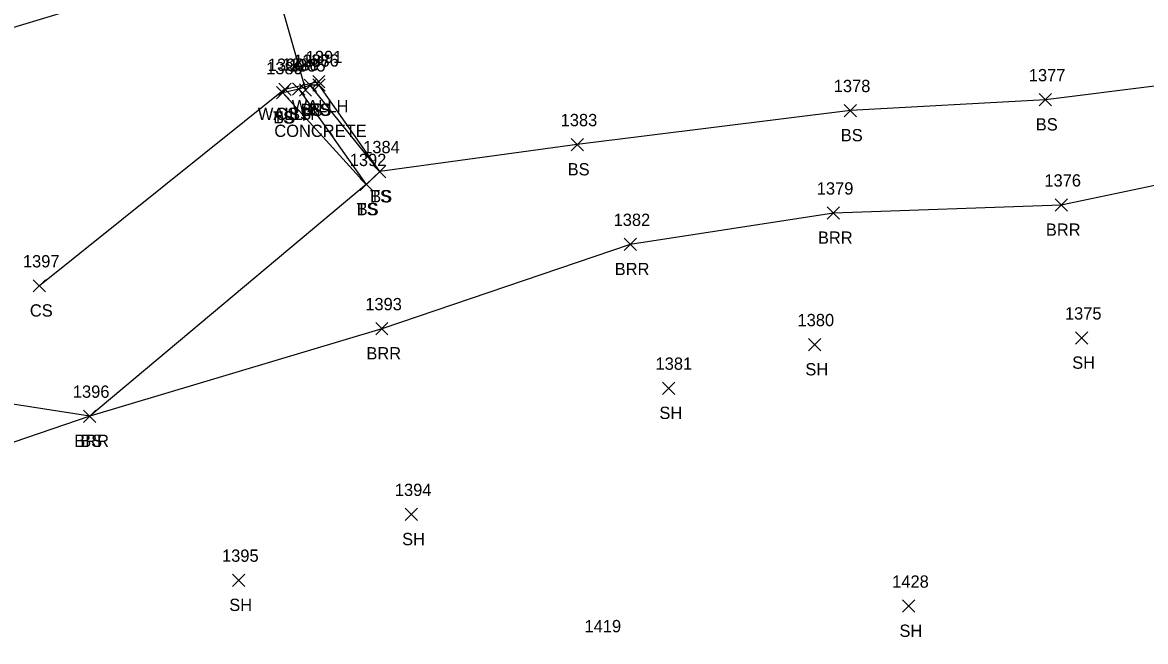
# Model space of a CAD drawing. Extents: x 1599569 to 1610055, y 642560 to 647860.
# Drawn here: x 1602081.3 to 1602263.8, y 647296.9 to 647397.5 of the extents above; entities that cross this region are included whole.
import ezdxf

# ---------------------------------------------------------------- set-up
doc = ezdxf.new("R2010")
doc.units = 0
for name, color, linetype in [('D_A', 7, 'Continuous'), ('D_C', 7, 'Continuous'), ('D_I', 7, 'Continuous'), ('D_TIC', 7, 'Continuous'), ('DCP', 7, 'Continuous'), ('DHW', 7, 'Continuous'), ('L_A', 7, 'Continuous'), ('L_I', 7, 'Continuous'), ('L_TIC', 7, 'Continuous'), ('LABL', 7, 'Continuous'), ('LELB', 7, 'Continuous')]:
    doc.layers.add(name, color=color, linetype=linetype)

msp = doc.modelspace()

# ---------------------------------------------------------------- linework, layer by layer
at = {"layer": 'D_TIC'}
for points in [[(1602128.44, 647386.93), (1602130.44, 647388.93)], [(1602130.44, 647386.93), (1602128.44, 647388.93)], [(1602122.92, 647385.68), (1602124.92, 647387.68)], [(1602124.92, 647385.68), (1602122.92, 647387.68)], [(1602126.27, 647385.57), (1602128.27, 647387.57)], [(1602128.27, 647385.57), (1602126.27, 647387.57)]]:
    msp.add_lwpolyline(points, dxfattribs=at)
at = {"layer": 'DCP'}
msp.add_lwpolyline([(1602103.84, 647468.61), (1602127.27, 647386.57)], dxfattribs=at)
at = {"layer": 'DHW'}
msp.add_lwpolyline([(1602123.92, 647386.68), (1602129.44, 647387.93)], dxfattribs=at)
at = {"layer": 'L_TIC'}
for points in [[(1602122.58, 647385.12), (1602124.58, 647387.12)], [(1602124.58, 647385.12), (1602122.58, 647387.12)], [(1602122.58, 647385.12), (1602124.58, 647387.12)], [(1602124.58, 647385.12), (1602122.58, 647387.12)], [(1602122.92, 647385.68), (1602124.92, 647387.68)], [(1602124.92, 647385.68), (1602122.92, 647387.68)], [(1602125.17, 647385.71), (1602127.17, 647387.71)], [(1602127.17, 647385.71), (1602125.17, 647387.71)], [(1602125.17, 647385.71), (1602127.17, 647387.71)], [(1602127.17, 647385.71), (1602125.17, 647387.71)], [(1602127.04, 647386.33), (1602129.04, 647388.33)], [(1602129.04, 647386.33), (1602127.04, 647388.33)], [(1602127.04, 647386.33), (1602129.04, 647388.33)], [(1602129.04, 647386.33), (1602127.04, 647388.33)], [(1602128.47, 647386.37), (1602130.47, 647388.37)], [(1602130.47, 647386.37), (1602128.47, 647388.37)], [(1602128.47, 647386.37), (1602130.47, 647388.37)], [(1602130.47, 647386.37), (1602128.47, 647388.37)], [(1602246.55, 647383.98), (1602248.55, 647385.98)], [(1602248.55, 647383.98), (1602246.55, 647385.98)], [(1602214.85, 647382.22), (1602216.85, 647384.22)], [(1602216.85, 647382.22), (1602214.85, 647384.22)], [(1602170.44, 647376.68), (1602172.44, 647378.68)], [(1602172.44, 647376.68), (1602170.44, 647378.68)], [(1602138.34, 647372.29), (1602140.34, 647374.29)], [(1602140.34, 647372.29), (1602138.34, 647374.29)], [(1602138.34, 647372.29), (1602140.34, 647374.29)], [(1602140.34, 647372.29), (1602138.34, 647374.29)], [(1602138.34, 647372.29), (1602140.34, 647374.29)], [(1602140.34, 647372.29), (1602138.34, 647374.29)], [(1602136.15, 647370.2), (1602138.15, 647372.2)], [(1602138.15, 647370.2), (1602136.15, 647372.2)], [(1602136.15, 647370.2), (1602138.15, 647372.2)], [(1602138.15, 647370.2), (1602136.15, 647372.2)], [(1602136.15, 647370.2), (1602138.15, 647372.2)], [(1602138.15, 647370.2), (1602136.15, 647372.2)], [(1602249.14, 647366.86), (1602251.14, 647368.86)], [(1602251.14, 647366.86), (1602249.14, 647368.86)], [(1602212.09, 647365.56), (1602214.09, 647367.56)], [(1602214.09, 647365.56), (1602212.09, 647367.56)], [(1602179.06, 647360.46), (1602181.06, 647362.46)], [(1602181.06, 647360.46), (1602179.06, 647362.46)], [(1602083.02, 647353.72), (1602085.02, 647355.72)], [(1602085.02, 647353.72), (1602083.02, 647355.72)], [(1602138.68, 647346.75), (1602140.68, 647348.75)], [(1602140.68, 647346.75), (1602138.68, 647348.75)], [(1602252.43, 647345.24), (1602254.43, 647347.24)], [(1602254.43, 647345.24), (1602252.43, 647347.24)], [(1602209.04, 647344.16), (1602211.04, 647346.16)], [(1602211.04, 647344.16), (1602209.04, 647346.16)], [(1602185.31, 647337.07), (1602187.31, 647339.07)], [(1602187.31, 647337.07), (1602185.31, 647339.07)], [(1602091.2, 647332.52), (1602093.2, 647334.52)], [(1602093.2, 647332.52), (1602091.2, 647334.52)], [(1602091.2, 647332.52), (1602093.2, 647334.52)], [(1602093.2, 647332.52), (1602091.2, 647334.52)], [(1602143.49, 647316.55), (1602145.49, 647318.55)], [(1602145.49, 647316.55), (1602143.49, 647318.55)], [(1602115.39, 647305.85), (1602117.39, 647307.85)], [(1602117.39, 647305.85), (1602115.39, 647307.85)], [(1602224.34, 647301.64), (1602226.34, 647303.64)], [(1602226.34, 647301.64), (1602224.34, 647303.64)]]:
    msp.add_lwpolyline(points, dxfattribs=at)
at = {"layer": 'LABL'}
msp.add_lwpolyline([(1602496.95, 647464.06), (1602459.22, 647439.98), (1602411.5, 647424.62), (1602337.77, 647394.37), (1602303.76, 647379.12), (1602250.14, 647367.86), (1602213.09, 647366.56), (1602180.06, 647361.46), (1602139.68, 647347.75), (1602092.2, 647333.52), (1602051.38, 647339.86)], dxfattribs=at)
at = {"layer": 'LELB'}
for points in [[(1601875.37, 647298.23), (1601899.27, 647311.46), (1601933.4, 647328.44), (1601966.96, 647349.6), (1601991.6, 647361.72), (1602007.33, 647369.55), (1602053.05, 647388.73), (1602108.48, 647405.48), (1602138.7, 647415.54), (1602162.27, 647422.58), (1602191.63, 647430.16), (1602222.72, 647436.69), (1602253.77, 647437.09), (1602274.71, 647434), (1602308.64, 647432.46), (1602335.54, 647436.29), (1602372.31, 647451.76), (1602413.17, 647464.59), (1602450.85, 647476.95), (1602485.79, 647485.59)], [(1602495.14, 647473.06), (1602458.34, 647453.1), (1602429.54, 647443.72), (1602409.1, 647434.56), (1602336.93, 647402.97), (1602302.05, 647391.78), (1602247.55, 647384.98), (1602215.85, 647383.22), (1602171.44, 647377.68), (1602139.34, 647373.29), (1602137.15, 647371.2), (1602092.2, 647333.52), (1602059.04, 647322.21), (1602026.95, 647294.33), (1601982.37, 647269.76)], [(1602139.34, 647373.29), (1602128.04, 647387.33), (1602126.17, 647386.71), (1602137.15, 647371.2)], [(1602129.47, 647387.37), (1602128.04, 647387.33)], [(1602139.34, 647373.29), (1602129.47, 647387.37)], [(1602123.92, 647386.68), (1602084.02, 647354.72)], [(1602126.17, 647386.71), (1602123.58, 647386.12)], [(1602123.58, 647386.12), (1602137.15, 647371.2)]]:
    msp.add_lwpolyline(points, dxfattribs=at)

# ---------------------------------------------------------------- texts
at = {"layer": 'D_A'}
for s, p in [('WALLH', (1602119.52, 647381.68)), ('WALLH', (1602125.03, 647382.93)), ('P', (1602126.65, 647381.57))]:
    msp.add_text(s, height=2, dxfattribs=at).set_placement(p)
at = {"layer": 'D_C'}
msp.add_text('CONCRETE', height=2, dxfattribs=at).set_placement((1602122.2, 647378.93))
at = {"layer": 'D_I'}
for s, p in [('1391', (1602127.31, 647390.93)), ('1390', (1602121.15, 647389.68)), ('1385', (1602124.58, 647389.57))]:
    msp.add_text(s, height=2, dxfattribs=at).set_placement(p)
at = {"layer": 'L_A'}
for s, p in [('CS', (1602122.37, 647381.68)), ('BS', (1602124.61, 647381.71)), ('BS', (1602124.61, 647381.71)), ('BS', (1602126.48, 647382.33)), ('BS', (1602126.48, 647382.33)), ('TS', (1602127.88, 647382.37)), ('BS', (1602127.91, 647382.37)), ('TS', (1602121.99, 647381.12)), ('BS', (1602122.03, 647381.12)), ('BS', (1602245.99, 647379.98)), ('BS', (1602214.29, 647378.22)), ('BS', (1602169.89, 647372.68)), ('TS', (1602137.75, 647368.29)), ('BS', (1602137.78, 647368.29)), ('BS', (1602137.78, 647368.29)), ('TS', (1602135.56, 647366.2)), ('BS', (1602135.59, 647366.2)), ('BS', (1602135.59, 647366.2)), ('BRR', (1602210.58, 647361.56)), ('BRR', (1602247.63, 647362.86)), ('BRR', (1602177.54, 647356.46)), ('CS', (1602082.46, 647349.72)), ('BRR', (1602137.17, 647342.75)), ('SH', (1602251.91, 647341.24)), ('SH', (1602208.53, 647340.16)), ('SH', (1602184.8, 647333.07)), ('BRR', (1602089.68, 647328.52)), ('BS', (1602090.64, 647328.52)), ('SH', (1602142.98, 647312.55)), ('SH', (1602114.88, 647301.85)), ('SH', (1602223.83, 647297.64))]:
    msp.add_text(s, height=2, dxfattribs=at).set_placement(p)
at = {"layer": 'L_I'}
for s, p in [('1389', (1602120.88, 647389.12)), ('1389', (1602120.88, 647389.12)), ('1390', (1602121.15, 647389.68)), ('1388', (1602123.48, 647389.71)), ('1388', (1602123.48, 647389.71)), ('1387', (1602125.35, 647390.33)), ('1387', (1602125.35, 647390.33)), ('1386', (1602126.73, 647390.37)), ('1386', (1602126.73, 647390.37)), ('1377', (1602244.86, 647387.98)), ('1378', (1602213.15, 647386.22)), ('1383', (1602168.75, 647380.68)), ('1384', (1602136.65, 647376.29)), ('1384', (1602136.65, 647376.29)), ('1384', (1602136.65, 647376.29)), ('1392', (1602134.46, 647374.2)), ('1392', (1602134.46, 647374.2)), ('1392', (1602134.46, 647374.2)), ('1376', (1602247.39, 647370.86)), ('1379', (1602210.39, 647369.56)), ('1382', (1602177.36, 647364.46)), ('1397', (1602081.33, 647357.72)), ('1393', (1602136.99, 647350.75)), ('1375', (1602250.73, 647349.24)), ('1380', (1602207.26, 647348.16)), ('1381', (1602184.18, 647341.07)), ('1396', (1602089.45, 647336.52)), ('1396', (1602089.45, 647336.52)), ('1394', (1602141.8, 647320.55)), ('1395', (1602113.7, 647309.85)), ('1428', (1602222.65, 647305.64)), ('1419', (1602172.63, 647298.39))]:
    msp.add_text(s, height=2, dxfattribs=at).set_placement(p)

doc.saveas('drawing.dxf')
